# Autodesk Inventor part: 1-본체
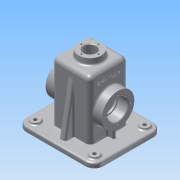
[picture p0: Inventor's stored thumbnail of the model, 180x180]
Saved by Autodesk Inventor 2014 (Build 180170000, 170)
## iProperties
Created: 2015-12
Part Number: 1-본체
Material: 알루미늄 6061
Document SubType Name: Modeling
Designer: Administrator
Density: 2.71 g/cm^3
Appearance: 알루미늄 - 평지
Mass: 804.853 g
Surface Area: 910.469 cm^2
Volume: 296.994 cm^3
Author: Administrator
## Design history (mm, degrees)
sketch "스케치1"
  geometry: L1 (-32.5, -32.5)-(32.5, -32.5); L2 (32.5, -32.5)-(32.5, 32.5); L3 (32.5, 32.5)-(-32.5, 32.5); L4 (-32.5, 32.5)-(-32.5, -32.5); L5 (-32.5, -32.5)-(32.5, 32.5); L6 (32.5, -32.5)-(-32.5, 32.5); 1 further point
  constraints: 12 end point, 2 midpoint, 2 parallel, 1 horizontal, 1 perpendicular
  dimensions: "d0" = 65 distance of L3.end L2.end; "d1" = 65 distance of L2.end L1.end
extrude "돌출1" new body sketch "스케치1" distance "d2" = 100; taper "d3" = 0 deg
feature "쉘1" dims "d4" = 5
sketch "스케치2"
  geometry: C1 r 20 at (0, 0); 1 further point
  constraints: 1 centre point, 1 coincident
  dimensions: "d5" = 40 diameter of C1
extrude "돌출2" join sketch "스케치2" distance "d6" = 10; taper "d7" = -5 deg
sketch "스케치3"
  geometry: L1 (-27.5, 27.5)-(-27.5, -27.5) reference; L2 (-27.5, -27.5)-(27.5, -27.5) reference; L3 (27.5, -27.5)-(27.5, 27.5) reference; L4 (27.5, 27.5)-(-27.5, 27.5) reference; L5 (-32.5, -32.5)-(-32.5, 32.5) reference; L6 (-32.5, 32.5)-(32.5, 32.5) reference; L7 (32.5, 32.5)-(32.5, -32.5) reference; L8 (32.5, -32.5)-(-32.5, -32.5) reference; L9 (65, -57.5)-(-65, -57.5); L10 (-65, -57.5)-(-65, 57.5); L11 (-65, 57.5)-(65, 57.5); L12 (65, 57.5)-(65, -57.5); L13 (65, -57.5)-(-65, 57.5); L14 (-65, -57.5)-(65, 57.5); L15 (27.5, 27.5)-(-27.5, 27.5); L16 (-27.5, 27.5)-(-27.5, -27.5); L17 (-27.5, -27.5)-(27.5, -27.5); L18 (27.5, -27.5)-(27.5, 27.5); 1 further point
  constraints: 20 end point, 4 parallel, 2 horizontal, 2 midpoint, 2 perpendicular
  dimensions: "d8" = 130 distance of L10.end L11.end; "d9" = 115 distance of L9.end L10.end
extrude "돌출3" join sketch "스케치3" distance "d10" = 8; taper "d11" = 0 deg
sketch "스케치4"
  geometry: L1 (-65, -57.5)-(65, -57.5) reference; L2 (65, -57.5)-(65, 57.5) reference; L3 (65, 57.5)-(-65, 57.5) reference; L4 (-65, 57.5)-(-65, -57.5) reference; L5 (-60, 52.5)-(60, 52.5); L6 (60, 52.5)-(60, -52.5); L7 (60, -52.5)-(-60, -52.5); L8 (-60, -52.5)-(-60, 52.5); L9 (-27.5, 27.5)-(27.5, 27.5); L10 (27.5, 27.5)-(27.5, -27.5); L11 (27.5, -27.5)-(-27.5, -27.5); L12 (-27.5, -27.5)-(-27.5, 27.5); 1 further point
  constraints: 16 end point, 2 parallel, 1 horizontal, 1 perpendicular, 3 other
  dimensions: "d12" = 5 distance between parallel lines of L3 L5
extrude "돌출4" join sketch "스케치4" distance "d13" = 2; taper "d14" = 0 deg
sketch "스케치5"
  geometry: L1 (-110, -20)-(-110, 85) reference; L2 (-100, -25)-(-100, 90) reference; C1 r 27.5 at (-55, 32.5); 2 further points
  constraints: 1 centre point, 1 horizontal alignment, 1 midpoint
  dimensions: "d15" = 55 diameter of C1; "d16" = 55 distance from line of C1.centre L1
extrude "돌출5" join sketch "스케치5" distance "d17" = 15; taper "d18" = 0 deg
sketch "스케치6"
  geometry: L1 (32.5, -32.5)-(32.5, 32.5) reference; L2 (-32.5, -32.5)-(32.5, -32.5) reference; L3 (32.5, 3)-(42.5, 3); L4 (42.5, 3)-(42.5, -3); L5 (42.5, -3)-(32.5, -3); L6 (32.5, 3)-(32.5, -3); L7 (27.5, -27.5)-(27.5, 27.5) reference; 2 further points
  constraints: 8 end point, 3 perpendicular, 2 point on line, 1 horizontal alignment, 1 midpoint, 1 parallel
  dimensions: "d19" = 6 distance of L3.end L4.end; "d20" = 15 distance between parallel lines of L4 L7
extrude "돌출6" join sketch "스케치6" stored distance "d21" = 15; taper "d22" = 0 deg
sketch "스케치7"
  geometry: L1 (19.125, 110)-(20, 100) reference; L2 (20, 100)-(32.5, 100) reference; L3 (32.5, 100)-(32.5, 0) reference; L4 (32.5, 0)-(57.5, 0) reference; L5 (57.5, 0)-(57.5, -8) reference; L6 (57.5, -8)-(52.5, -8) reference; L7 (52.5, -8)-(52.5, -10) reference; L8 (52.5, -10)-(27.5, -10) reference; L9 (27.5, -10)-(27.5, 95) reference; L10 (27.5, 95)-(-27.5, 95) reference; L11 (-27.5, 95)-(-27.5, -10) reference; L12 (-27.5, -10)-(-52.5, -10) reference; L13 (-52.5, -10)-(-52.5, -8) reference; L14 (-52.5, -8)-(-57.5, -8) reference; L15 (-57.5, -8)-(-57.5, 0) reference; L16 (-57.5, 0)-(-32.5, 0) reference; L17 (-32.5, 0)-(-32.5, 100) reference; L18 (-32.5, 100)-(-20, 100) reference; L19 (-20, 100)-(-19.125, 110) reference; L20 (-19.125, 110)-(19.125, 110) reference; L21 (47.5, 0)-(32.5, 85.069); 1 further point
  constraints: 2 end point, 2 point on line
  dimensions: "d23" = 10 distance of L4.end L21.start; "d24" = 100 deg angle of L4 L21
feature "리브1" sketch "스케치7" dims "d25" = 1, "d26" = 10, "d27" = 0, "d28" = 0, "d29" = 1, "d30" = 1
fillet "모깎기1" dims "d31" = 15
sketch "스케치8"
  geometry: C1 r 7.5 at (-50, 42.5); C2 r 7.5 at (50, 42.5); C3 r 7.5 at (50, -42.5); C4 r 7.5 at (-50, -42.5); A1 r 15 centre (50, -42.5) between (50, -57.5) and (65, -42.5) reference; A2 r 15 centre (50, 42.5) between (65, 42.5) and (50, 57.5) reference; A3 r 15 centre (-50, 42.5) between (-50, 57.5) and (-65, 42.5) reference; A4 r 15 centre (-50, -42.5) between (-65, -42.5) and (-50, -57.5) reference; 1 further point
  constraints: 4 centre point, 4 coincident, 3 equal radius
  dimensions: "d32" = 15 diameter of C1
extrude "돌출7" join sketch "스케치8" distance "d33" = 3; taper "d34" = 0 deg
sketch "스케치9"
  geometry: C1 r 7.5 at (0, 0) reference; C2 r 3 at (0, 0); 1 further point
  constraints: 1 centre point, 1 coincident
  dimensions: "d35" = 6 diameter of C2
extrude "돌출8" cut sketch "스케치9" distance "d36" = 20; taper "d37" = 0 deg
fillet "모깎기2" dims "d44" = 10
sketch "스케치10"
  geometry: C1 r 27.5 at (0, 0) reference; C2 r 17.5 at (0, 0); 1 further point
  constraints: 1 centre point, 1 coincident
  dimensions: "d45" = 35 diameter of C2
extrude "돌출9" cut sketch "스케치10" distance "d46" = 17; taper "d47" = 0 deg
sketch "스케치11"
  geometry: C1 r 17.5 at (0, 0) reference; C2 r 15 at (0, 0); 1 further point
  constraints: 1 centre point, 1 coincident
  dimensions: "d48" = 30 diameter of C2
extrude "돌출10" cut sketch "스케치11" stored distance "d49" = 0; taper "d50" = 0 deg
sketch "스케치12" dims "d51" = 42
  geometry: C1 r 17.5 at (0, 0) reference; C2 r 27.5 at (0, 0) reference; 3 further points
  constraints: 2 horizontal alignment, 1 coincident, 2 other
hole "구멍1" sketch "스케치12" at (-21, 0) diameter "d52" = 3.242; stored, may be unused: countersink angle "d56" = 90 deg, drill point angle "d58" = 118 deg; dims "d53" = 8, "d54" = 4, "d55" = 2, "d57" = 10
sketch "스케치13"
  geometry: C1 r 19.125 at (0, 0) reference; C2 r 10.5 at (0, 0)
  constraints: 1 centre point, 1 coincident
  dimensions: "d62" = 21 diameter of C2
extrude "돌출11" cut sketch "스케치13" stored distance "d63" = 0; taper "d64" = 0 deg
sketch "스케치14" dims "d65" = 29
  geometry: C1 r 10.5 at (0, 0) reference; C2 r 19.125 at (0, 0) reference; 2 further points
  constraints: 2 vertical alignment, 1 coincident, 2 other
hole "구멍2" sketch "스케치14" at (0, 14.5) diameter "d66" = 2.459; stored, may be unused: countersink angle "d70" = 90 deg, drill point angle "d72" = 118 deg; dims "d67" = 7, "d68" = 4, "d69" = 2, "d71" = 9
fillet "모깎기3" dims "d76" = 8
fillet "모깎기4" dims "d77" = 8
chamfer "모따기1" distance "d78" = 1; stored, may be unused: second distance "d79" = 2, angle "d80" = 45 deg
fillet "모깎기5" dims "d81" = 3
fillet "모깎기6" dims "d82" = 3
fillet "모깎기7" dims "d83" = 3
fillet "모깎기8" dims "d84" = 3
fillet "모깎기9" dims "d85" = 3
fillet "모깎기10" dims "d86" = 3
fillet "모깎기11" dims "d87" = 3
fillet "모깎기12" dims "d88" = 1
fillet "모깎기13" dims "d89" = 3
fillet "모깎기14" dims "d90" = 3
fillet "모깎기15" dims "d91" = 3
sketch "스케치15"
  geometry: L1 (0, -8)-(91, -8) reference; L2 (-18, 5.375)-(-18, 43.625) reference; 2 further points
  constraints: 1 other
  dimensions: "d92" = 32.5 distance from line of point (8, 24.5) L1; "d93" = 26 distance from line of L2 point (8, 24.5)
feature "엠보싱1" sketch "스케치15" dims "d8" = 130, "d9" = 115, "d94" = 0.5, "d95" = 0
fillet "모깎기16" dims "d96" = 0.3
node "솔리드1"
mirror "대칭1"
mirror "대칭2"
mirror "대칭3"
pattern_linear "직사각형 패턴1" dims "d40" = 100, "d43" = 85
mirror "대칭4"
pattern_circular "원형 패턴1" dims angle "d60" = 360 deg
mirror "대칭5"
pattern_circular "원형 패턴2" dims angle "d74" = 360 deg
node "작업 평면1"
node "절단 모서리 투영1"
node "절단 모서리 투영2"
